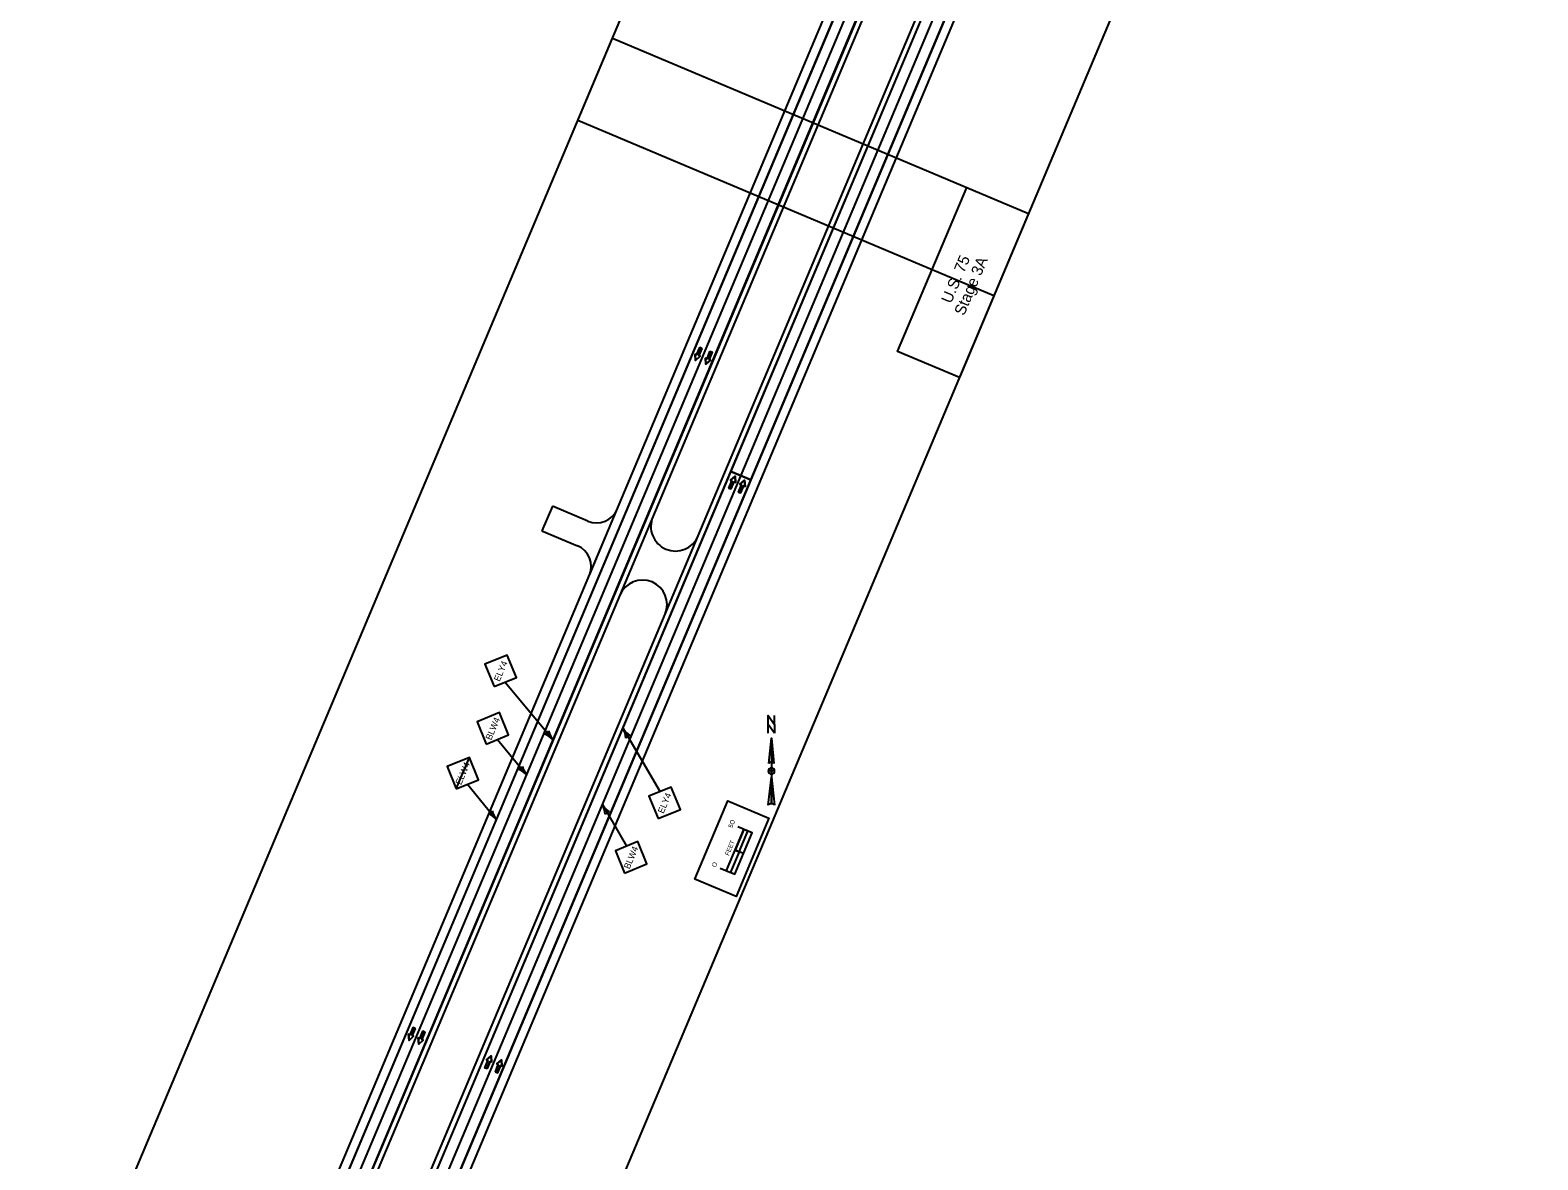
# Model space of a CAD drawing. Extents: x 14104283 to 14120882, y 8635219 to 8671666.
# Drawn here: x 14117444 to 14119130, y 8665999 to 8667263 of the extents above; entities that cross this region are included whole.
import ezdxf

# ---------------------------------------------------------------- set-up
doc = ezdxf.new("R2010")
doc.units = 0
for name, color, linetype in [('Cell', 7, 'Continuous'), ('dsnCellsNorthArrow', 7, 'Continuous'), ('dsnCellsScaleBlock', 7, 'Continuous'), ('dsnNonPlotable', 7, 'Continuous'), ('dsnPaintExistingEdgeLineRightWhite', 7, 'Continuous'), ('dsnPaintPlaceBrokenLineWhite', 7, 'Continuous'), ('dsnPaintPlaceEdgeLineLeftYellow', 7, 'Continuous'), ('dsnPaintPlaceEdgeLineRightWhite', 7, 'Continuous'), ('dsnPaintRemoveDoubleCenterLineYellow', 7, 'Continuous'), ('dsnShadingPaved', 7, 'Continuous'), ('dsnStdLabel', 7, 'Continuous'), ('dsnStgShadingPrevPav', 7, 'Continuous'), ('dsnTextOverlapEven', 7, 'Continuous')]:
    doc.layers.add(name, color=color, linetype=linetype)

msp = doc.modelspace()

# ---------------------------------------------------------------- linework, layer by layer
at = {"layer": 'Cell'}
for points in [[(14118192.7, 8666908), (14118195, 8666907.1), (14118191.7, 8666899), (14118193.4, 8666898.3), (14118188.1, 8666893.7), (14118187.6, 8666900.6), (14118189.3, 8666899.9)], [(14118204.2, 8666903.6), (14118206.5, 8666902.7), (14118203.2, 8666894.6), (14118204.9, 8666893.9), (14118199.6, 8666889.3), (14118199.1, 8666896.2), (14118200.9, 8666895.5)], [(14118227.7, 8666749.8), (14118225.4, 8666750.8), (14118228.7, 8666758.9), (14118227, 8666759.6), (14118232.3, 8666764.2), (14118232.8, 8666757.2), (14118231, 8666757.9)], [(14118238.5, 8666745.3), (14118236.2, 8666746.2), (14118239.5, 8666754.3), (14118237.8, 8666755), (14118243, 8666759.6), (14118243.5, 8666752.7), (14118241.8, 8666753.4)], [(14117872, 8666147.3), (14117874.3, 8666146.3), (14117871, 8666138.2), (14117872.7, 8666137.5), (14117867.5, 8666132.9), (14117867, 8666139.9), (14117868.7, 8666139.2)], [(14117882.8, 8666143), (14117885.1, 8666142), (14117881.8, 8666133.9), (14117883.5, 8666133.2), (14117878.3, 8666128.6), (14117877.7, 8666135.6), (14117879.5, 8666134.9)], [(14117954.8, 8666101.3), (14117952.5, 8666102.3), (14117955.8, 8666110.4), (14117954.1, 8666111.1), (14117959.4, 8666115.7), (14117959.9, 8666108.7), (14117958.2, 8666109.4)], [(14117966.4, 8666096.7), (14117964.1, 8666097.7), (14117967.4, 8666105.8), (14117965.6, 8666106.5), (14117970.9, 8666111.1), (14117971.4, 8666104.1), (14117969.7, 8666104.8)]]:
    msp.add_lwpolyline(points, close=True, dxfattribs=at)
for points in [[(14118189.3, 8666899.9), (14118187.6, 8666900.6), (14118188.1, 8666893.7), (14118193.4, 8666898.3), (14118191.7, 8666899), (14118195, 8666907.1), (14118192.7, 8666908), (14118189.3, 8666899.9)], [(14118200.9, 8666895.5), (14118199.1, 8666896.2), (14118199.6, 8666889.3), (14118204.9, 8666893.9), (14118203.2, 8666894.6), (14118206.5, 8666902.7), (14118204.2, 8666903.6), (14118200.9, 8666895.5)], [(14118231, 8666757.9), (14118232.8, 8666757.2), (14118232.3, 8666764.2), (14118227, 8666759.6), (14118228.7, 8666758.9), (14118225.4, 8666750.8), (14118227.7, 8666749.8), (14118231, 8666757.9)], [(14118241.8, 8666753.4), (14118243.5, 8666752.7), (14118243, 8666759.6), (14118237.8, 8666755), (14118239.5, 8666754.3), (14118236.2, 8666746.2), (14118238.5, 8666745.3), (14118241.8, 8666753.4)], [(14117868.7, 8666139.2), (14117867, 8666139.9), (14117867.5, 8666132.9), (14117872.7, 8666137.5), (14117871, 8666138.2), (14117874.3, 8666146.3), (14117872, 8666147.3), (14117868.7, 8666139.2)], [(14117879.5, 8666134.9), (14117877.7, 8666135.6), (14117878.3, 8666128.6), (14117883.5, 8666133.2), (14117881.8, 8666133.9), (14117885.1, 8666142), (14117882.8, 8666143), (14117879.5, 8666134.9)], [(14117958.2, 8666109.4), (14117959.9, 8666108.7), (14117959.4, 8666115.7), (14117954.1, 8666111.1), (14117955.8, 8666110.4), (14117952.5, 8666102.3), (14117954.8, 8666101.3), (14117958.2, 8666109.4)], [(14117969.7, 8666104.8), (14117971.4, 8666104.1), (14117970.9, 8666111.1), (14117965.6, 8666106.5), (14117967.4, 8666105.8), (14117964.1, 8666097.7), (14117966.4, 8666096.7), (14117969.7, 8666104.8)]]:
    msp.add_lwpolyline(points, dxfattribs=at)
at = {"layer": 'dsnCellsNorthArrow'}
for p, q in [((14118273, 8666470.9), (14118275.8, 8666442.7)), ((14118273, 8666470.9), (14118273, 8666397.7)), ((14118270.1, 8666442.7), (14118270.1, 8666442.7)), ((14118270.2, 8666443), (14118270.8, 8666443.6)), ((14118269.4, 8666396.2), (14118273, 8666427.2)), ((14118273, 8666430.8), (14118273, 8666430.8))]:
    msp.add_line(p, q, dxfattribs=at)
msp.add_lwpolyline([(14118276.5, 8666476.5), (14118269.4, 8666486.4), (14118269.4, 8666496.2), (14118276.5, 8666486.4)], close=True, dxfattribs=at)
for points in [[(14118269.4, 8666476.5), (14118269.4, 8666496.2), (14118276.5, 8666486.4), (14118276.5, 8666496.2)], [(14118270.1, 8666442.7), (14118273, 8666470.9), (14118273, 8666444.1)], [(14118273, 8666430.8), (14118273, 8666434.3), (14118269.4, 8666434.3)], [(14118276.5, 8666434.3), (14118273, 8666434.3), (14118273, 8666437.8)], [(14118273, 8666397.7), (14118273, 8666427.2), (14118276.5, 8666396.2)]]:
    msp.add_lwpolyline(points, dxfattribs=at)
for centre, radius, start, end in [((14118273, 8666434.3), 3.52, 90, 180), ((14118273, 8666434.3), 3.52, 180, 270), ((14118273, 8666440.6), 3.52, 90.0204, 143.1257), ((14118273, 8666440.6), 3.52, 36.8481, 90.0218), ((14118273, 8666434.3), 3.52, 0, 90), ((14118273, 8666434.3), 3.52, 270, 360), ((14118273, 8666392.5), 5.1, 89.9894, 133.619), ((14118273, 8666392.5), 5.11, 46.4021, 90.0006)]:
    msp.add_arc(centre, radius, start, end, dxfattribs=at)
at = {"layer": 'dsnCellsScaleBlock'}
msp.add_line((14118241.7, 8666341.9), (14118232.4, 8666345.8), dxfattribs=at)
msp.add_line((14118241.7, 8666341.9), (14118232.4, 8666345.8), dxfattribs=at)
for points in [[(14118233.4, 8666293.9), (14118187.3, 8666313.3), (14118224.2, 8666400.9), (14118270.2, 8666381.4)], [(14118187.3, 8666313.3), (14118224.2, 8666400.9), (14118270.2, 8666381.4), (14118233.4, 8666293.9)], [(14118233.4, 8666293.9), (14118187.3, 8666313.3), (14118224.2, 8666400.9), (14118270.2, 8666381.4)], [(14118237, 8666343.9), (14118246.7, 8666366.9), (14118242.2, 8666368.9), (14118232.4, 8666345.8)], [(14118232, 8666318.9), (14118241.7, 8666341.9), (14118237, 8666343.9), (14118227.3, 8666320.9)]]:
    msp.add_lwpolyline(points, close=True, dxfattribs=at)
for points in [[(14118215.8, 8666325.7), (14118232, 8666318.9), (14118251.4, 8666365), (14118235.2, 8666371.8)], [(14118222.7, 8666322.8), (14118242.2, 8666368.9)]]:
    msp.add_lwpolyline(points, dxfattribs=at)
at = {"layer": 'dsnNonPlotable'}
for points in [[(14118056.5, 8667161.9), (14118665.1, 8668606.4), (14119130.4, 8668410.4), (14118521.9, 8666965.8)], [(14117486.7, 8665809.5), (14118095.3, 8667254.1), (14118560.7, 8667058), (14117952.1, 8665613.5)]]:
    msp.add_lwpolyline(points, close=True, dxfattribs=at)
at = {"layer": 'dsnPaintExistingEdgeLineRightWhite'}
msp.add_line((14110924.4, 8649364.5), (14118862.5, 8668214.7), dxfattribs=at)
at = {"layer": 'dsnPaintPlaceBrokenLineWhite'}
for p, q in [((14114932.5, 8658913.4), (14118951.7, 8668457.6)), ((14110829.5, 8649404.5), (14118424.3, 8667439.6))]:
    msp.add_line(p, q, dxfattribs=at)
at = {"layer": 'dsnPaintPlaceEdgeLineLeftYellow'}
for p, q in [((14115900.9, 8661244), (14118817.4, 8668169.6)), ((14118435.4, 8667434.9), (14115816.1, 8661215.2))]:
    msp.add_line(p, q, dxfattribs=at)
at = {"layer": 'dsnPaintPlaceEdgeLineRightWhite'}
msp.add_line((14118413.2, 8667444.3), (14115798.8, 8661235.7), dxfattribs=at)
at = {"layer": 'dsnPaintRemoveDoubleCenterLineYellow'}
msp.add_line((14114932.5, 8658913.4), (14118493, 8667368.2), dxfattribs=at)
at = {"layer": 'dsnShadingPaved'}
for p, q in [((14118227.7, 8666769.2), (14118940.7, 8668462.2)), ((14118962.8, 8668452.9), (14118249.8, 8666759.9)), ((14115901.2, 8661244.5), (14118227.7, 8666769.2)), ((14118227.7, 8666769.2), (14118249.8, 8666759.9)), ((14118249.8, 8666759.9), (14118227.7, 8666769.2)), ((14118249.8, 8666759.9), (14115923.3, 8661235.2))]:
    msp.add_line(p, q, dxfattribs=at)
for points in [[(14118413.2, 8667444.3), (14110818.4, 8649409.2), (14109142.6, 8645431.4)], [(14109164.7, 8645422.1), (14110840.5, 8649399.8), (14118435.4, 8667434.9)]]:
    msp.add_lwpolyline(points, dxfattribs=at)
at = {"layer": 'dsnStdLabel'}
for p, q in [((14117975.2, 8666533.8), (14118028.6, 8666469.1)), ((14118107.1, 8666481.8), (14118148.4, 8666411.1)), ((14117966.4, 8666469.5), (14117999.4, 8666429.5)), ((14117920.3, 8666414.3), (14117935.1, 8666449.5)), ((14117932.8, 8666419.4), (14117965.4, 8666379.8)), ((14118083.8, 8666396.6), (14118110.9, 8666350.2))]:
    msp.add_line(p, q, dxfattribs=at)
for points in [[(14117962.7, 8666528.8), (14117987.7, 8666538.9), (14117977.5, 8666563.9), (14117952.5, 8666553.8)], [(14117953.9, 8666464.4), (14117978.9, 8666474.6), (14117968.7, 8666499.6), (14117943.7, 8666489.4)], [(14117920.3, 8666414.3), (14117945.3, 8666424.5), (14117935.1, 8666449.5), (14117910.1, 8666439.3)], [(14118146.1, 8666381), (14118171.1, 8666391.2), (14118160.9, 8666416.2), (14118135.9, 8666406)], [(14118108.6, 8666320.1), (14118133.6, 8666330.3), (14118123.4, 8666355.3), (14118098.4, 8666345.1)]]:
    msp.add_lwpolyline(points, close=True, dxfattribs=at)
for centre, radius, start, end in [((14118087.2, 8666470.3), 22.9, 2.1566, 30.2279), ((14118126.9, 8666493.4), 22.9, 210.2277, 238.299), ((14118016.1, 8666483.7), 8.86, 292.8385, 328.307), ((14118011.2, 8666454.2), 22.9, 40.5727, 68.6439), ((14118046.1, 8666484), 22.9, 192.5015, 220.5728), ((14118116.8, 8666465.2), 8.86, 102.4935, 137.962), ((14117986.9, 8666444.1), 8.86, 292.8385, 328.307), ((14117982, 8666414.6), 22.9, 40.5727, 68.6439), ((14118016.8, 8666444.5), 22.9, 192.5015, 220.5728), ((14117952.9, 8666394.4), 8.86, 292.8385, 328.307), ((14117948, 8666364.9), 22.9, 40.5727, 68.6439), ((14117982.9, 8666394.7), 22.9, 192.5015, 220.5728), ((14118063.9, 8666385.1), 22.9, 2.1566, 30.2279), ((14118103.6, 8666408.2), 22.9, 210.2277, 238.299), ((14118093.5, 8666380), 8.86, 102.4935, 137.962)]:
    msp.add_arc(centre, radius, start, end, dxfattribs=at)
at = {"layer": 'dsnStgShadingPrevPav'}
for p, q in [((14115895.6, 8661246.8), (14118811.5, 8668171)), ((14118848.4, 8668155.5), (14115932.5, 8661231.3)), ((14118653, 8668013.6), (14115794, 8661224.5)), ((14115816.1, 8661215.2), (14118675.1, 8668004.3)), ((14115816.1, 8661215.2), (14118675.1, 8668004.3)), ((14118680.7, 8668002), (14115821.7, 8661212.9)), ((14110809.2, 8649413), (14118404, 8667448.1)), ((14118413.2, 8667444.3), (14110818.4, 8649409.2)), ((14118027.9, 8666730.6), (14118016.2, 8666703)), ((14118067.7, 8666713.9), (14118027.9, 8666730.6)), ((14118069.4, 8666653.5), (14118100.4, 8666727.2)), ((14118140.2, 8666718.6), (14118103.3, 8666631)), ((14118016.2, 8666703), (14118056.1, 8666686.2)), ((14118154, 8666609.7), (14118190.9, 8666697.3))]:
    msp.add_line(p, q, dxfattribs=at)
for centre, radius, start, end in [((14118077.4, 8666736.9), 25, 247.1633, 337.1633), ((14118165.6, 8666707.9), 27.5, 157.1633, 247.1633), ((14118046.4, 8666663.2), 25, 337.1633, 67.1633), ((14118165.6, 8666707.9), 27.5, 247.1633, 337.1633), ((14118128.7, 8666620.4), 27.5, 67.1633, 157.1633), ((14118128.7, 8666620.4), 27.5, 337.1633, 67.1633)]:
    msp.add_arc(centre, radius, start, end, dxfattribs=at)
at = {"layer": 'dsnTextOverlapEven'}
for points in [[(14118560.7, 8667058), (14118483.3, 8666874.4), (14118414.2, 8666903.5), (14118491.6, 8667087.1)], [(14118414.2, 8666903.5), (14118491.6, 8667087.1), (14118560.7, 8667058), (14118483.3, 8666874.4)]]:
    msp.add_lwpolyline(points, close=True, dxfattribs=at)

# ---------------------------------------------------------------- texts
at = {"layer": 'dsnCellsScaleBlock'}
for s, p in [('5O', (14118229, 8666370)), ('FEET', (14118225.3, 8666339.1)), ('O', (14118210.6, 8666326.1))]:
    msp.add_text(s, height=5, rotation=67.1547, dxfattribs=at).set_placement(p)
at = {"layer": 'dsnStdLabel'}
for s, p in [('ELY4', (14117968.8, 8666533.8)), ('BLW4', (14117959.4, 8666468.2)), ('ELW4', (14117925.8, 8666418.1)), ('ELY4', (14118152.2, 8666386.1)), ('BLW4', (14118114.1, 8666323.9))]:
    msp.add_text(s, height=7.2, rotation=67.1547, dxfattribs=at).set_placement(p)
at = {"layer": 'dsnTextOverlapEven'}
for s, p in [('U.S. 75', (14118473.9, 8666956.5)), ('Stage 3A', (14118488.5, 8666942.9))]:
    msp.add_text(s, height=12.5, rotation=67.1547, dxfattribs=at).set_placement(p)

doc.saveas('drawing.dxf')
